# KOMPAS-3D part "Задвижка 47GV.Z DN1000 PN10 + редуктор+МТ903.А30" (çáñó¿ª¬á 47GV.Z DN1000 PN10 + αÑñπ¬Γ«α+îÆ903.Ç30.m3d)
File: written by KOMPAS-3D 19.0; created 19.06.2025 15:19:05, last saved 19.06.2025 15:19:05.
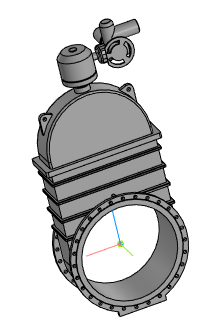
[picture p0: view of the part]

Document properties: Полное имя файла: Задвижка 47GV.Z DN1000 PN10 + редуктор+МТ903.А30.a3d

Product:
- Part/product: Задвижка 47GV.Z DN1000 PN10 + редуктор+МТ903.А30
    Масса: 4662.41

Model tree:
1. Операция без истории:1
